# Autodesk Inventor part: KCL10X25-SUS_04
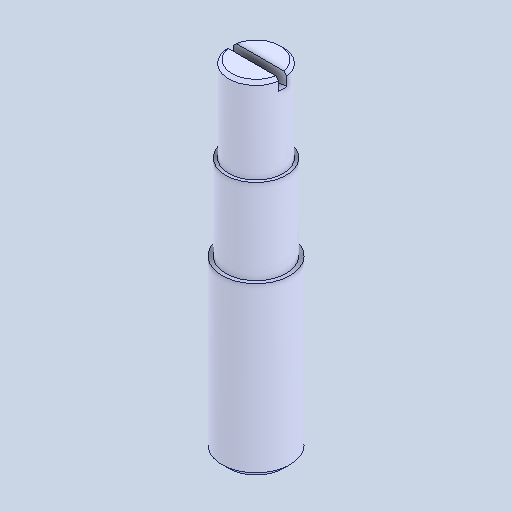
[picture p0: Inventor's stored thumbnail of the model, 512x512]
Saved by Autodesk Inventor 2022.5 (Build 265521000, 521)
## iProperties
Created: 2024-08
Part Number: KCL10X25-SUS_04
Material: 一般
Document SubType Name: Modeling
Designer: ImaoCorp
Density: 1 g/cm^3
Appearance: 既定
Author: ImaoCorp
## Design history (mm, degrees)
feature "KCL10X25-SUS_04"
node "ソリッド1"
